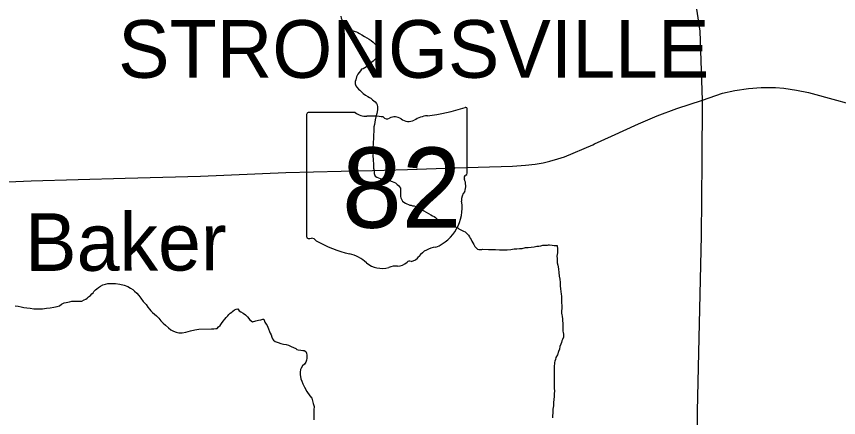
# Model space of a CAD drawing. Extents: x 2010165 to 2382125, y 1060529 to 1407316.
# Drawn here: x 2145283 to 2152412, y 1205287 to 1208766 of the extents above; entities that cross this region are included whole.
import ezdxf

# ---------------------------------------------------------------- set-up
doc = ezdxf.new("R2010")
doc.units = 0
for name, color, linetype in [('GM_X_Corporation_Text', 7, 'Continuous'), ('GM_X_Minor_River', 7, 'Continuous'), ('GM_X_Minor_River_Text', 7, 'Continuous'), ('GM_X_State_Location', 7, 'Continuous'), ('GM_X_State_Route', 7, 'Continuous'), ('GM_X_State_Shield', 7, 'Continuous'), ('GM_X_US_Route', 7, 'Continuous')]:
    doc.layers.add(name, color=color, linetype=linetype)

msp = doc.modelspace()

# ---------------------------------------------------------------- linework, layer by layer
at = {"layer": 'GM_X_Minor_River'}
for points in [[(2148095.9, 1208767.5), (2148100.1, 1208751.5), (2148106.4, 1208733.5), (2148114.7, 1208711.6), (2148124.9, 1208693.6), (2148133.1, 1208683.7), (2148141.2, 1208673.8), (2148151.4, 1208661.9), (2148165.5, 1208656), (2148179.6, 1208648.2), (2148203.8, 1208640.4), (2148219.8, 1208636.6), (2148231.9, 1208632.8), (2148244, 1208626.9), (2148258.1, 1208619), (2148278.3, 1208605.2), (2148300.5, 1208593.5), (2148322.8, 1208579.7), (2148340.9, 1208569.9), (2148359.1, 1208556.1), (2148377.3, 1208544.3), (2148393.6, 1208526.4), (2148409.9, 1208506.5), (2148418.2, 1208480.6), (2148418.6, 1208454.5), (2148407.1, 1208412.2), (2148399.2, 1208400.1), (2148377.5, 1208377.8), (2148349.7, 1208359.3), (2148318, 1208328.9), (2148290.2, 1208312.5), (2148276.2, 1208308.3), (2148266.4, 1208294.1), (2148254.6, 1208279.9), (2148242.7, 1208265.8), (2148233, 1208243.6), (2148225.4, 1208215.4), (2148219.5, 1208201.3), (2148219.8, 1208181.2), (2148226, 1208165.2), (2148234.2, 1208153.3), (2148250.4, 1208135.5), (2148260.6, 1208125.6), (2148272.8, 1208113.7), (2148291, 1208097.8), (2148309.2, 1208084), (2148329.4, 1208072.2), (2148345.6, 1208062.4), (2148355.7, 1208056.5), (2148369.9, 1208042.6), (2148382, 1208032.8), (2148394.1, 1208024.9), (2148406.3, 1208011), (2148410.5, 1207999), (2148412.7, 1207981), (2148413.1, 1207956.9), (2148409.5, 1207922.8), (2148399.9, 1207894.5), (2148394.2, 1207868.4), (2148390.4, 1207850.3), (2148386.7, 1207828.2), (2148383, 1207808.1), (2148383.2, 1207790), (2148381.5, 1207767.9), (2148379.9, 1207739.8), (2148378.2, 1207713.7), (2148373.4, 1207621.4), (2148373.6, 1207607.3), (2148375.7, 1207595.3), (2148375.9, 1207581.3), (2148374.2, 1207563.2), (2148374.3, 1207549.2)], [(2148374.3, 1207549.2), (2148376.5, 1207535.1), (2148376.8, 1207513.1), (2148379.1, 1207491), (2148379.3, 1207473), (2148379.5, 1207463), (2148379.6, 1207450.9), (2148381.8, 1207440.9), (2148384, 1207422.9), (2148386.2, 1207404.9), (2148388.4, 1207394.9), (2148392.6, 1207380.9), (2148408.7, 1207371), (2148422.8, 1207367.2), (2148436.9, 1207361.4), (2148455, 1207357.6), (2148469.1, 1207353.7), (2148483.1, 1207351.9), (2148493.2, 1207348), (2148505.2, 1207344.1), (2148521.3, 1207342.3), (2148531.4, 1207338.4), (2148541.4, 1207334.6), (2148555.5, 1207328.7), (2148569.6, 1207322.9), (2148585.8, 1207309), (2148596, 1207301.1), (2148606.1, 1207289.2), (2148612.3, 1207275.2), (2148614.7, 1207251.2), (2148613, 1207223.1), (2148613.3, 1207203), (2148615.4, 1207193), (2148623.7, 1207175.1), (2148631.8, 1207163.1), (2148642, 1207155.2), (2148656.1, 1207147.4), (2148694.4, 1207129.8), (2148706.4, 1207127.9), (2148718.5, 1207124.1), (2148732.5, 1207122.2), (2148746.7, 1207116.4), (2148764.9, 1207102.6), (2148795.1, 1207090.9), (2148817.2, 1207081.1), (2148837.4, 1207069.4), (2148855.6, 1207055.5), (2148875.8, 1207043.8), (2148891.9, 1207035.9), (2148906.1, 1207030.1), (2148918.2, 1207022.2), (2148932.4, 1207008.3), (2148954.6, 1206994.6), (2148972.8, 1206982.8), (2148995, 1206971), (2149011.1, 1206965.2), (2149023.1, 1206961.3), (2149033.2, 1206957.4), (2149043.3, 1206955.5), (2149053.3, 1206951.6), (2149067.4, 1206945.8), (2149083.5, 1206942), (2149095.6, 1206938.1), (2149107.7, 1206934.2), (2149119.8, 1206924.4), (2149142, 1206912.6), (2149160.1, 1206904.8), (2149174.3, 1206896.9), (2149192.5, 1206879.1), (2149202.7, 1206869.2), (2149210.9, 1206855.3), (2149219, 1206843.3), (2149225.2, 1206831.4), (2149233.4, 1206817.4), (2149241.6, 1206801.5), (2149249.8, 1206787.5), (2149258, 1206771.6), (2149270.3, 1206757.7), (2149282.4, 1206747.8), (2149292.4, 1206745.9), (2149308.5, 1206744.1), (2149318.5, 1206744.2), (2149328.5, 1206746.4), (2149376.6, 1206744.9), (2149404.7, 1206743.3), (2149438.7, 1206743.7), (2149472.8, 1206742.1), (2149506.9, 1206742.6), (2149538.9, 1206742.9), (2149570.9, 1206745.3), (2149598.9, 1206749.7), (2149623, 1206750), (2149645, 1206752.3), (2149669, 1206754.6), (2149696.9, 1206760.9), (2149721, 1206763.2), (2149747, 1206765.6), (2149773, 1206767.9), (2149795, 1206772.2), (2149813, 1206774.4), (2149831, 1206776.6)], [(2149831, 1206776.6), (2149848.9, 1206780.8), (2149869, 1206783.1), (2149887, 1206783.3), (2149897, 1206785.4), (2149907, 1206785.6), (2149929.1, 1206781.8), (2149945.1, 1206780), (2149955.1, 1206780.1), (2149971.2, 1206778.3), (2149973.6, 1206746.3), (2149974, 1206716.2), (2149970.4, 1206688.1), (2149970.7, 1206666), (2149972.9, 1206647.9), (2149973.2, 1206627.9), (2149977.4, 1206609.9), (2149979.6, 1206593.9), (2149983.9, 1206573.8), (2149986.3, 1206545.8), (2149990.7, 1206511.8), (2149995, 1206487.7), (2149997.4, 1206457.7), (2149997.8, 1206429.6), (2150000.1, 1206403.5), (2150006.8, 1206357.5), (2150009, 1206339.4), (2150009.3, 1206319.4), (2150009.5, 1206299.3), (2150009.8, 1206281.3), (2150012.1, 1206259.2), (2150012.4, 1206233.2), (2150010.7, 1206211.1), (2150010.9, 1206193), (2150013.1, 1206179), (2150015.3, 1206165), (2150017.6, 1206140.9), (2150017.8, 1206124.9), (2150020.1, 1206106.9), (2150020.5, 1206074.8), (2150020.7, 1206056.7), (2150021, 1206036.6), (2150023.1, 1206024.6), (2150027.3, 1206010.6), (2150025.7, 1205982.6), (2150017.9, 1205964.4), (2150012.1, 1205952.3), (2150010.3, 1205938.2), (2150004.5, 1205922.1), (2149996.7, 1205901.9), (2149991, 1205879.8), (2149983.2, 1205859.6), (2149973.6, 1205831.4), (2149961.9, 1205807.2), (2149958.1, 1205789.1), (2149952.3, 1205775), (2149948.4, 1205764.9), (2149947, 1205722.8), (2149945.3, 1205698.7), (2149945.4, 1205686.6), (2149945.7, 1205668.6), (2149946, 1205646.5), (2149946.3, 1205620.5), (2149946.6, 1205596.4), (2149947, 1205568.3), (2149947.4, 1205540.2), (2149947.7, 1205516.1), (2149946, 1205494.1), (2149946.3, 1205470), (2149944.6, 1205443.9), (2149940.9, 1205417.8), (2149939.3, 1205389.7), (2149935.7, 1205359.5), (2149934, 1205339.4), (2149934.2, 1205323.4), (2149932.4, 1205305.3), (2149932.7, 1205285.2)], [(2145271.9, 1206255.2), (2145298, 1206251.6), (2145324.1, 1206245.8), (2145348.2, 1206242.1), (2145374.3, 1206238.4), (2145402.4, 1206236.8), (2145434.5, 1206231.2), (2145476.6, 1206229.7), (2145508.6, 1206230.1), (2145542.6, 1206234.5), (2145576.7, 1206238.9), (2145608.6, 1206243.3), (2145636.6, 1206249.7), (2145656.6, 1206255.9), (2145674.4, 1206270.2), (2145698.3, 1206280.5), (2145714.3, 1206284.8), (2145728.3, 1206286.9), (2145744.3, 1206291.1), (2145764.2, 1206295.4), (2145788.3, 1206295.7), (2145810.3, 1206296), (2145850.4, 1206296.4), (2145870.3, 1206306.7), (2145884.2, 1206314.9), (2145896.1, 1206321.1), (2145908, 1206333.3), (2145925.9, 1206345.5), (2145937.7, 1206359.7), (2145947.6, 1206369.9), (2145955.5, 1206380), (2145967.3, 1206394.2), (2145981.2, 1206404.4), (2145995.1, 1206414.6), (2146012.9, 1206426.8), (2146032.8, 1206437.1), (2146054.8, 1206443.4), (2146076.8, 1206449.7), (2146108.8, 1206450.1), (2146140.9, 1206448.5), (2146179, 1206442.9), (2146217.2, 1206435.4), (2146249.4, 1206423.7), (2146271.6, 1206409.9), (2146291.8, 1206398.2), (2146308, 1206384.3), (2146326.3, 1206364.5), (2146344.6, 1206344.6), (2146362.9, 1206322.8), (2146383.3, 1206293), (2146407.7, 1206267.2), (2146422, 1206245.3), (2146436.3, 1206227.4), (2146448.5, 1206211.5), (2146462.7, 1206197.6), (2146478.9, 1206183.8), (2146497.2, 1206168), (2146517.5, 1206148.2), (2146535.8, 1206126.3), (2146554.1, 1206106.5), (2146574.4, 1206086.7), (2146602.7, 1206064.9), (2146623, 1206047.1), (2146645.2, 1206035.4), (2146667.3, 1206027.6), (2146691.4, 1206021.9), (2146719.5, 1206022.2), (2146751.4, 1206028.6), (2146791.4, 1206039.2), (2146829.3, 1206047.7), (2146865.3, 1206052.1), (2146973.4, 1206057.5), (2146995.5, 1206057.7), (2147013.5, 1206057.9), (2147023.5, 1206060.1), (2147035.4, 1206072.3), (2147049.2, 1206086.5), (2147061, 1206102.7), (2147074.8, 1206122.9), (2147090.6, 1206139.1), (2147100.4, 1206153.3), (2147116.2, 1206169.5), (2147124.1, 1206179.7), (2147136, 1206191.8), (2147149.8, 1206202.1), (2147159.8, 1206210.2), (2147173.7, 1206220.4)], [(2147173.7, 1206220.4), (2147189.6, 1206226.6), (2147201.6, 1206228.8), (2147215.8, 1206212.9), (2147230, 1206203), (2147248.2, 1206191.2), (2147268.4, 1206177.4), (2147286.6, 1206159.6), (2147307, 1206135.8), (2147329.3, 1206116), (2147359.2, 1206124.4), (2147383.2, 1206130.7), (2147401.2, 1206134.9), (2147419.1, 1206139.1), (2147429.2, 1206139.3), (2147437.5, 1206113.3), (2147447.7, 1206097.4), (2147455.9, 1206085.4), (2147462.1, 1206071.5), (2147482.8, 1206019.6), (2147491, 1206003.6), (2147497.3, 1205983.6), (2147503.5, 1205969.7), (2147511.7, 1205957.7), (2147527.9, 1205945.9), (2147552, 1205938.2), (2147576.2, 1205930.4), (2147600.3, 1205924.7), (2147622.4, 1205919), (2147642.5, 1205913.2), (2147666.7, 1205903.4), (2147686.8, 1205893.7), (2147705, 1205885.9), (2147715.1, 1205878), (2147727.1, 1205874.1), (2147749.2, 1205870.4), (2147767.3, 1205868.6), (2147779.3, 1205868.7), (2147791.5, 1205858.8), (2147797.6, 1205844.9), (2147801.9, 1205828.9), (2147802.2, 1205802.8), (2147798.4, 1205784.7), (2147792.6, 1205768.6), (2147780.9, 1205748.4), (2147765, 1205734.1), (2147751.3, 1205715.9), (2147745.4, 1205703.8), (2147743.7, 1205679.7), (2147744, 1205657.6), (2147746.2, 1205643.6), (2147750.5, 1205623.6), (2147758.7, 1205603.7), (2147767.1, 1205579.7), (2147781.5, 1205549.8), (2147802, 1205511.9), (2147828.5, 1205476.1), (2147844.8, 1205454.2), (2147851.1, 1205432.2), (2147857.5, 1205408.3), (2147863.8, 1205382.3), (2147862.2, 1205354.1), (2147861.3, 1205267.9)]]:
    msp.add_lwpolyline(points, dxfattribs=at)
at = {"layer": 'GM_X_State_Route'}
for points in [[(2151232.9, 1208040), (2151405.4, 1208100.9), (2151512.1, 1208123.7), (2151632, 1208141.3), (2151741.3, 1208149.1), (2151865, 1208149.1), (2151937.9, 1208143.2), (2152048.6, 1208126.9), (2152152.8, 1208105.5), (2152393.2, 1208038.5), (2153317.5, 1207786.4), (2153538.7, 1207725)], [(2150297.1, 1207660.3), (2150444.5, 1207726.6), (2150676.9, 1207833.3), (2150839.5, 1207902.9), (2151009.8, 1207968.5), (2151232.9, 1208040)], [(2145010.5, 1207323.1), (2145410.6, 1207339.2), (2146224.7, 1207362.3), (2146878.6, 1207379.3), (2147620.2, 1207411.4), (2148099.4, 1207423.2), (2148370.9, 1207430.3), (2148675.6, 1207439.4), (2149087.7, 1207451.8), (2149585.3, 1207467), (2149697.7, 1207475.5), (2149781.2, 1207485.7), (2149849.3, 1207496.8), (2149908, 1207510.4), (2149977.9, 1207530), (2150034.9, 1207549.6), (2150282.3, 1207653.6), (2150297.1, 1207660.3)]]:
    msp.add_lwpolyline(points, dxfattribs=at)
at = {"layer": 'GM_X_State_Shield'}
for p, q in [((2147799.7, 1207915.2), (2147799.7, 1206858.6)), ((2148221.1, 1207933.4), (2147813.4, 1207933.4)), ((2149191.9, 1207406.9), (2149191.9, 1207959.6)), ((2149191.7, 1207407), (2149191.9, 1207406.9))]:
    msp.add_line(p, q, dxfattribs=at)
for centre, radius, start, end in [((2148696, 1209374), 1476.4, 275.84447, 288.90645), ((2149176.4, 1207961.9), 15.5, 351.86209, 97.738), ((2147815.7, 1207917.5), 16.1, 98.1301, 188.1301), ((2148318.2, 1208056.1), 156.4, 231.61951, 271.11188), ((2148370.1, 1207340.2), 561.6, 80.48669, 94.98827), ((2148884.3, 1207610.7), 297, 97.34618, 120.76885), ((2148497.6, 1207923), 45.1, 219.79206, 297.10237), ((2148563.8, 1207800.8), 93.8, 54.46668, 119.14113), ((2148684.9, 1207968.3), 112.9, 233.85621, 294.82819), ((2149175.3, 1207404.7), 16.6, 289.60381, 7.73413), ((2149188.3, 1207366.3), 24, 107.94398, 210.33697), ((2149035.7, 1207296.4), 144, 340.03296, 23.64957), ((2149247.4, 1207175.6), 104.8, 136.8065, 186.92959), ((2148778.7, 1207105.2), 369.3, 292.30889, 8.98584), ((2147815.8, 1206856.3), 16.3, 171.95839, 258.30661), ((2147818.3, 1206964.4), 124.2, 267.33899, 280.60386), ((2147843.7, 1206797.6), 44.8, 29.74838, 93.27175), ((2148409, 1207747), 1066.1, 240.41292, 257.1985), ((2148934.4, 1206562), 202.2, 94.40312, 142.57675), ((2148091.1, 1206383.9), 333.6, 47.18416, 75.83597), ((2148451.9, 1206792.4), 211.7, 230.70037, 286.29184), ((2148589.6, 1206713.3), 112.8, 268.77702, 315.54927), ((2148691.7, 1206610.9), 31.8, 65.75173, 132.64842), ((2148678.1, 1206756.2), 119.3, 282.87319, 323.27711), ((2148574.2, 1206427.1), 173.9, 85.69512, 111.20995)]:
    msp.add_arc(centre, radius, start, end, dxfattribs=at)
at = {"layer": 'GM_X_US_Route'}
for points in [[(2151232.9, 1208040), (2151212, 1208637.1), (2151120.9, 1209254.7)], [(2151229.3, 1207511.9), (2151232.9, 1208040)], [(2151197.3, 1204185.3), (2151197, 1204201.3), (2151194.3, 1204348.9), (2151192.9, 1204659.8), (2151189.4, 1205004.7), (2151189.9, 1205341.6), (2151224.9, 1206861.9), (2151229.3, 1207511.9)]]:
    msp.add_lwpolyline(points, dxfattribs=at)

# ---------------------------------------------------------------- texts
at = {"layer": 'GM_X_Corporation_Text'}
msp.add_text('STRONGSVILLE', height=500, rotation=0.00001, dxfattribs=at).set_placement((2146164.7, 1208233.9))
at = {"layer": 'GM_X_Minor_River_Text'}
msp.add_text('Baker', height=500.27, rotation=0.15698, dxfattribs=at).set_placement((2145358.8, 1206558.1))
at = {"layer": 'GM_X_State_Location'}
for s in ['s', 'r']:
    msp.add_text(s, height=1, dxfattribs=at).set_placement((2148480.1, 1207316.7))
msp.add_text('82', height=1, rotation=0.00001, dxfattribs=at).set_placement((2148228.3, 1207243.9))
at = {"layer": 'GM_X_State_Shield'}
msp.add_text('82', height=696.1, dxfattribs=at).set_placement((2148106.6, 1206933.1))

doc.saveas('drawing.dxf')
